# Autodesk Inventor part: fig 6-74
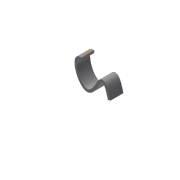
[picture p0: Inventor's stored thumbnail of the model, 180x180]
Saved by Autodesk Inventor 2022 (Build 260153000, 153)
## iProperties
Part Number: fig 6-74
Document SubType Name: Modeling
Created: 2002-12
Designer: deepak
Density: 1 g/cm^3
Material: Generic
Appearance: Default
Control State: 0
Master: False
Checked Out: False
Shininess: 64.0
Length Units: 11269
Angle Units: 11279
Time Units: 11290
Mass Units: 11283
Length Display Precision: 3
Angle Display Precision: 2
Compacted: True
Density: 0.0
Volumn: 0.0
Area: 0.0
PropertySet Name: Model Information
Author: deepak
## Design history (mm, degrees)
sketch "Sketch1"
  geometry: 5 further points
  constraints: 5 other
extrude_surface "ExtrusionSrf1" sketch "Sketch1" dims "d0" = 20, "d1" = 0
thicken "Thicken2" dims "d6" = 4, "d7" = 4
body "Solid1"
body "Srf1"
